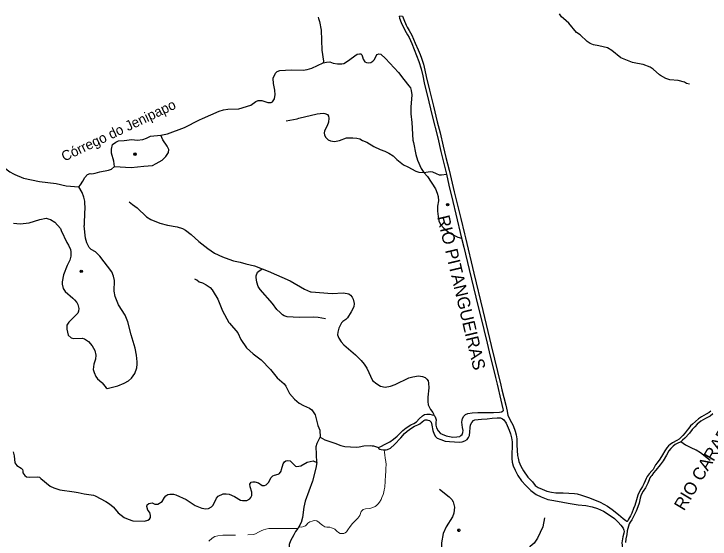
# Model space of a CAD drawing. Extents: x 267.7 to 296, y 7537.7 to 7565.8.
# Drawn here: x 273.16 to 278.74, y 7561.36 to 7565.57 of the extents above; entities that cross this region are included whole.
import ezdxf
from ezdxf.enums import TextEntityAlignment as Align

# ---------------------------------------------------------------- set-up
doc = ezdxf.new("R2010")
doc.units = 0
doc.header["$LTSCALE"] = 0.04
doc.header["$PDMODE"] = 32
doc.header["$PDSIZE"] = 0.02
doc.linetypes.add('SHORT_DASHED', pattern=[2.7, 1.5, -1.2])
for name, color, linetype, lineweight in [('1', 7, 'Continuous', 25), ('2', 7, 'Continuous', 25), ('21', 7, 'SHORT_DASHED', 13), ('62', 7, 'SHORT_DASHED', 13), ('7', 7, 'Continuous', 25)]:
    doc.layers.add(name, color=color, linetype=linetype, lineweight=lineweight)
doc.layers.add('54', color=7, linetype='Continuous')
doc.layers.add('61', color=7, linetype='Continuous')

msp = doc.modelspace()

# ---------------------------------------------------------------- linework, layer by layer
at = {"layer": '1'}
for points in [[(276.2507, 7565.5559), (276.2542, 7565.5396), (276.2661, 7565.5059), (276.2958, 7565.445), (276.3181, 7565.4069), (276.33, 7565.3861), (276.3532, 7565.3365), (276.3716, 7565.29), (276.4097, 7565.1914), (276.427, 7565.1335), (276.4394, 7565.078), (276.4523, 7565.022), (276.4899, 7564.8685), (276.5147, 7564.7575), (276.5598, 7564.5797), (276.585, 7564.4708), (276.6289, 7564.2909)], [(276.2787, 7565.5563), (276.2871, 7565.5302), (276.3064, 7565.4846), (276.3142, 7565.4671), (276.3322, 7565.4407), (276.3526, 7565.4046), (276.3797, 7565.3385), (276.4031, 7565.2868), (276.4182, 7565.249), (276.4302, 7565.2183), (276.4458, 7565.1708), (276.4572, 7565.1239), (276.4686, 7565.0717), (276.4945, 7564.9641), (276.5251, 7564.8336), (276.5558, 7564.7086), (276.5786, 7564.6203), (276.6027, 7564.5145), (276.6255, 7564.4219), (276.6508, 7564.321), (276.6922, 7564.1473), (276.7439, 7563.9333), (276.774, 7563.8113), (276.7818, 7563.7784)], [(276.6289, 7564.2909), (276.6499, 7564.2003), (276.6821, 7564.0705), (276.7059, 7563.969), (276.7511, 7563.7762)], [(276.7818, 7563.7784), (276.8485, 7563.4958), (276.92, 7563.1977), (276.9879, 7562.9152), (277.0661, 7562.5996), (277.0745, 7562.5624), (277.1057, 7562.4386), (277.1159, 7562.3901)], [(276.7511, 7563.7762), (276.7678, 7563.7055), (276.8119, 7563.5267), (276.8297, 7563.4489), (276.8822, 7563.237), (276.9015, 7563.1532), (276.955, 7562.9363), (276.9719, 7562.8665), (277.0224, 7562.6589), (277.0353, 7562.6059), (277.0665, 7562.4772), (277.0828, 7562.4078), (277.0848, 7562.3994), (277.0843, 7562.393)]]:
    msp.add_lwpolyline(points, dxfattribs=at)
at = {"layer": '2'}
for points in [[(276.528, 7562.3573), (276.5357, 7562.3502), (276.5434, 7562.3371), (276.5464, 7562.3206), (276.544, 7562.2981), (276.544, 7562.2767), (276.5493, 7562.2578), (276.5624, 7562.2317), (276.5831, 7562.2116), (276.595, 7562.2051), (276.6269, 7562.1932), (276.6803, 7562.182), (276.7122, 7562.1831), (276.7359, 7562.1879), (276.7454, 7562.1938), (276.7549, 7562.2039), (276.7602, 7562.2187), (276.7626, 7562.2341), (276.7596, 7562.259), (276.7537, 7562.3016), (276.7549, 7562.3176), (276.759, 7562.3318), (276.7691, 7562.3502), (276.7827, 7562.3632), (276.8011, 7562.3703), (276.8354, 7562.3774), (276.8822, 7562.3786), (277.0066, 7562.3798), (277.0558, 7562.3822), (277.07, 7562.3851), (277.0843, 7562.393)], [(277.1159, 7562.3901), (277.1165, 7562.3875), (277.1208, 7562.3592), (277.1262, 7562.3442), (277.1502, 7562.2997), (277.1634, 7562.2739), (277.1809, 7562.2306), (277.1893, 7562.1993), (277.1947, 7562.1693), (277.1947, 7562.12), (277.1971, 7562.0737), (277.2001, 7562.0359), (277.2037, 7562.0124), (277.2109, 7561.9854), (277.2247, 7561.9505), (277.2476, 7561.9127), (277.283, 7561.8616), (277.3185, 7561.8231), (277.3413, 7561.7955), (277.3648, 7561.778), (277.3954, 7561.7636), (277.4339, 7561.7486), (277.4706, 7561.7402), (277.5066, 7561.7366), (277.5655, 7561.7342), (277.6551, 7561.7299), (277.6785, 7561.7269), (277.7122, 7561.7179), (277.7759, 7561.6957), (277.8612, 7561.6596), (277.9213, 7561.6284), (277.9574, 7561.6007), (278.0091, 7561.5617), (278.0445, 7561.5304), (278.0668, 7561.5136), (278.074, 7561.5094), (278.08, 7561.5082)], [(278.7474, 7562.3898), (278.7336, 7562.3781), (278.7112, 7562.3669), (278.6728, 7562.3445), (278.6499, 7562.3285), (278.6243, 7562.3077), (278.6004, 7562.2854), (278.5865, 7562.2726), (278.5716, 7562.255), (278.5588, 7562.2385), (278.5423, 7562.2172), (278.5226, 7562.1953), (278.5061, 7562.1761), (278.4938, 7562.1655), (278.4746, 7562.1543), (278.4411, 7562.1367), (278.4214, 7562.1223), (278.4086, 7562.1111), (278.3958, 7562.0962), (278.3798, 7562.0723), (278.3612, 7562.0403), (278.3404, 7562.0057), (278.3169, 7561.9753), (278.3052, 7561.9604), (278.2935, 7561.9385), (278.285, 7561.9231), (278.2765, 7561.913), (278.2541, 7561.889), (278.237, 7561.8661), (278.229, 7561.8506), (278.2216, 7561.8325), (278.2125, 7561.8085), (278.2019, 7561.7872), (278.188, 7561.7654), (278.1726, 7561.7414), (278.1635, 7561.7169), (278.1513, 7561.6802), (278.1385, 7561.6327), (278.1294, 7561.6093), (278.115, 7561.5725), (278.1033, 7561.5502), (278.0889, 7561.5235), (278.0836, 7561.5118), (278.08, 7561.5082)], [(276.0867, 7562.1002), (276.1087, 7562.1097), (276.1347, 7562.1239), (276.1762, 7562.1446), (276.2046, 7562.166), (276.236, 7562.1897), (276.252, 7562.2051), (276.2792, 7562.2347), (276.3059, 7562.2572), (276.345, 7562.2809), (276.3681, 7562.2915), (276.3906, 7562.3058), (276.4125, 7562.3277), (276.4368, 7562.3526), (276.454, 7562.3626), (276.4735, 7562.3668), (276.4966, 7562.3656), (276.5162, 7562.362), (276.528, 7562.3573)], [(276.131, 7562.0789), (276.1466, 7562.0789), (276.1584, 7562.0825), (276.1803, 7562.0943), (276.2123, 7562.1239), (276.2656, 7562.1766), (276.2941, 7562.2116), (276.3142, 7562.2311), (276.3515, 7562.256), (276.3734, 7562.2702), (276.4001, 7562.2809), (276.4161, 7562.2886), (276.435, 7562.304), (276.4487, 7562.3152), (276.4605, 7562.3194), (276.4718, 7562.3206), (276.4818, 7562.3188), (276.4949, 7562.3146), (276.5002, 7562.3105), (276.5067, 7562.3028), (276.5126, 7562.2791), (276.5209, 7562.2353), (276.531, 7562.2068), (276.5416, 7562.1867), (276.5547, 7562.1749), (276.5843, 7562.1636), (276.6192, 7562.1506), (276.6548, 7562.1482), (276.7336, 7562.1423), (276.7561, 7562.1446), (276.7762, 7562.1518), (276.7952, 7562.1642), (276.8076, 7562.1778), (276.8153, 7562.1938), (276.8183, 7562.2234), (276.82, 7562.2554), (276.823, 7562.2809), (276.8319, 7562.2998), (276.8455, 7562.3146), (276.8585, 7562.3212), (276.9107, 7562.3271), (276.9569, 7562.3289), (276.9954, 7562.3336), (277.0351, 7562.3366), (277.0623, 7562.3354), (277.0801, 7562.3294), (277.0901, 7562.3212), (277.1073, 7562.2939), (277.1334, 7562.2382), (277.144, 7562.2086), (277.1523, 7562.1754), (277.1565, 7562.1441), (277.1559, 7562.102), (277.1541, 7562.054), (277.1541, 7562.0114), (277.1571, 7561.9823), (277.1654, 7561.951), (277.1814, 7561.9178), (277.2021, 7561.874), (277.2323, 7561.8319), (277.2661, 7561.7934), (277.3063, 7561.7537), (277.3496, 7561.7217), (277.3893, 7561.7034), (277.4414, 7561.6832), (277.4894, 7561.6749), (277.561, 7561.6619), (277.6061, 7561.653), (277.6848, 7561.6406), (277.7464, 7561.6341), (277.798, 7561.6234), (277.8388, 7561.6104), (277.8874, 7561.5879), (277.9182, 7561.5689), (277.9774, 7561.5286), (278.0065, 7561.4996), (278.0278, 7561.4765), (278.0444, 7561.451), (278.0515, 7561.4356)], [(278.765, 7562.3674), (278.7415, 7562.3498), (278.7064, 7562.3322), (278.6691, 7562.3093), (278.6393, 7562.2854), (278.6201, 7562.2656), (278.5988, 7562.2438), (278.5769, 7562.215), (278.5391, 7562.1735), (278.5221, 7562.157), (278.5067, 7562.1435)], [(278.5067, 7562.1435), (278.4773, 7562.1303), (278.4629, 7562.1218), (278.4475, 7562.1106), (278.4283, 7562.092), (278.4123, 7562.0717), (278.3931, 7562.0371), (278.3649, 7561.9929), (278.3431, 7561.9609), (278.3084, 7561.9162), (278.2898, 7561.8954), (278.2743, 7561.8751), (278.2663, 7561.8661), (278.2599, 7561.8554), (278.253, 7561.8384), (278.2429, 7561.8139), (278.2338, 7561.792), (278.2237, 7561.7761), (278.2056, 7561.7499), (278.1912, 7561.7196), (278.1832, 7561.6929), (278.1726, 7561.6535), (278.1635, 7561.6226), (278.1502, 7561.5896), (278.1289, 7561.5454), (278.114, 7561.5198), (278.1007, 7561.5012), (278.0927, 7561.4862), (278.0873, 7561.4687), (278.0788, 7561.4319), (278.0751, 7561.4015), (278.0682, 7561.3674), (278.0655, 7561.3387)], [(276.0867, 7562.1002), (276.0862, 7562.0937), (276.0885, 7562.0902), (276.0968, 7562.0842), (276.1069, 7562.0819), (276.1258, 7562.0789), (276.131, 7562.0789)], [(278.0515, 7561.4356), (278.0527, 7561.4262), (278.0515, 7561.4131), (278.0438, 7561.3841), (278.0361, 7561.3349), (278.0373, 7561.3172), (278.0402, 7561.2881), (278.0473, 7561.2301), (278.0639, 7561.1703), (278.074, 7561.1371), (278.0835, 7561.0885), (278.0918, 7561.0423), (278.0965, 7561.0026), (278.0947, 7560.9444)]]:
    msp.add_lwpolyline(points, dxfattribs=at)
at = {"layer": '21'}
for points in [[(275.4471, 7561.4626), (275.4699, 7561.4615), (275.4836, 7561.466), (275.4996, 7561.4721), (275.508, 7561.4797), (275.5186, 7561.4912), (275.5354, 7561.5018), (275.5537, 7561.5087), (275.5704, 7561.5125), (275.5917, 7561.511), (275.6108, 7561.4988), (275.6184, 7561.4889), (275.639, 7561.4729), (275.6565, 7561.4637), (275.6725, 7561.4599), (275.6953, 7561.4592), (275.7075, 7561.4546), (275.7258, 7561.4493), (275.7349, 7561.4439), (275.7517, 7561.4295), (275.7654, 7561.418), (275.7776, 7561.4104), (275.7898, 7561.4089), (275.8065, 7561.4104), (275.8179, 7561.4158), (275.8278, 7561.4241), (275.8393, 7561.4386), (275.8591, 7561.466), (275.8781, 7561.4896), (275.8979, 7561.511), (275.9185, 7561.533), (275.9345, 7561.5529), (275.9413, 7561.5696), (275.9467, 7561.5848), (275.9543, 7561.5947), (275.9634, 7561.6008), (275.9817, 7561.6077), (276.0152, 7561.6107), (276.0396, 7561.6168), (276.0586, 7561.626), (276.0693, 7561.6351), (276.0815, 7561.6481), (276.0921, 7561.6618), (276.1074, 7561.6823), (276.1134, 7561.6983), (276.1233, 7561.7219), (276.1279, 7561.7417), (276.1317, 7561.7585), (276.1363, 7561.7798), (276.1393, 7561.8286), (276.1409, 7561.8765), (276.1439, 7561.9055), (276.1454, 7561.9306), (276.1462, 7561.9618), (276.1431, 7561.987), (276.1393, 7562.0136), (276.1355, 7562.041), (276.1325, 7562.0601), (276.131, 7562.0789)], [(274.7266, 7561.3487), (274.7517, 7561.3723), (274.773, 7561.3853), (274.7974, 7561.3922), (274.8385, 7561.3952), (275.083, 7561.4005), (275.1005, 7561.4074), (275.1234, 7561.4203), (275.1462, 7561.431), (275.1637, 7561.4378), (275.1828, 7561.4439), (275.2079, 7561.4493), (275.2422, 7561.4508), (275.3435, 7561.45), (275.4381, 7561.4484)]]:
    msp.add_lwpolyline(points, dxfattribs=at)
msp.add_point((276.729, 7561.4355), dxfattribs=at)
at = {"layer": '54'}
for p in [(274.1337, 7564.4501), (276.6391, 7564.0448), (273.7043, 7563.5115)]:
    msp.add_point(p, dxfattribs=at)
at = {"layer": '62'}
msp.add_line((276.2507, 7565.5559), (276.2787, 7565.5563), dxfattribs=at)
at = {"layer": '7'}
msp.add_line((276.0443, 7562.1123), (276.0867, 7562.1002), dxfattribs=at)
for points in [[(278.5776, 7565.0106), (278.5773, 7565.0107), (278.5528, 7565.0167), (278.5368, 7565.0272), (278.487, 7565.0394), (278.4188, 7565.047), (278.3887, 7565.0552), (278.3439, 7565.0796), (278.3371, 7565.0858), (278.2865, 7565.1317), (278.2623, 7565.147), (278.2072, 7565.1684), (278.1607, 7565.1771), (278.1198, 7565.1847), (278.0274, 7565.2212), (277.9555, 7565.2795), (277.9192, 7565.301), (277.8518, 7565.3187), (277.8069, 7565.3263), (277.7819, 7565.3363), (277.7578, 7565.3517), (277.7005, 7565.4055), (277.6705, 7565.4261), (277.6099, 7565.5003), (277.5669, 7565.5369), (277.5518, 7565.5495), (277.5353, 7565.574)], [(275.6019, 7565.5467), (275.6049, 7565.5381), (275.6132, 7565.5145), (275.6266, 7565.4435), (275.6323, 7565.2827), (275.6434, 7565.1957), (275.6428, 7565.1809)], [(275.6428, 7565.1809), (275.6685, 7565.1883), (275.6942, 7565.1893), (275.7231, 7565.1794), (275.7571, 7565.1742), (275.7915, 7565.1742), (275.8064, 7565.1771), (275.8369, 7565.194), (275.9147, 7565.2503), (275.9322, 7565.2543), (275.9425, 7565.2533), (275.9517, 7565.2451), (275.9576, 7565.2312), (275.9631, 7565.2126), (275.9771, 7565.1902), (275.9894, 7565.1839), (276.0069, 7565.1814), (276.0232, 7565.1839), (276.0411, 7565.1944), (276.0543, 7565.2078), (276.0677, 7565.2379)], [(276.0677, 7565.2379), (276.0759, 7565.2482), (276.0893, 7565.2533), (276.1043, 7565.2504), (276.1425, 7565.2161), (276.2457, 7565.1058), (276.2875, 7565.0477), (276.3286, 7564.9989), (276.3407, 7564.9823), (276.3471, 7564.9599), (276.3536, 7564.9244), (276.3441, 7564.8263), (276.3441, 7564.7725), (276.352, 7564.7035), (276.3617, 7564.5618), (276.3656, 7564.5421), (276.3841, 7564.448), (276.3974, 7564.4014), (276.4278, 7564.3355), (276.4486, 7564.3021)], [(274.341, 7564.6029), (274.396, 7564.614), (274.5299, 7564.6637), (274.652, 7564.7251), (274.6747, 7564.7365), (274.8084, 7564.7942), (274.8427, 7564.8048), (274.8771, 7564.8095), (274.9651, 7564.8136), (275.0622, 7564.8414), (275.1025, 7564.8725), (275.1211, 7564.8805), (275.1503, 7564.8797), (275.1991, 7564.8638), (275.2261, 7564.8632), (275.2366, 7564.8705), (275.2522, 7564.8947), (275.2524, 7564.8963), (275.2571, 7564.9261), (275.2539, 7564.9636), (275.2428, 7565.0158), (275.2426, 7565.0554), (275.2426, 7565.0581), (275.26, 7565.0993), (275.2743, 7565.1136), (275.2936, 7565.1214), (275.3855, 7565.1264), (275.483, 7565.124), (275.5149, 7565.1278), (275.5522, 7565.1405), (275.6428, 7565.1809)], [(275.3444, 7564.7168), (275.4333, 7564.7343), (275.4459, 7564.7373), (275.5939, 7564.7728), (275.6412, 7564.7776), (275.6559, 7564.776), (275.677, 7564.7669), (275.6841, 7564.7537), (275.6873, 7564.7377), (275.6852, 7564.7051), (275.675, 7564.6766), (275.6532, 7564.6375), (275.6499, 7564.6192), (275.6514, 7564.6056), (275.6598, 7564.5859), (275.6828, 7564.5636), (275.6996, 7564.5558), (275.7315, 7564.5511), (275.774, 7564.5588), (275.8301, 7564.5797), (275.8787, 7564.5813), (275.9127, 7564.5789), (275.9355, 7564.5725), (275.9584, 7564.5594), (275.9919, 7564.5459), (276.0471, 7564.5119), (276.0985, 7564.487), (276.1368, 7564.4743), (276.146, 7564.4699), (276.1693, 7564.4588), (276.2036, 7564.4361), (276.231, 7564.4079), (276.2849, 7564.3639), (276.3201, 7564.3491), (276.3846, 7564.3147), (276.4091, 7564.3061), (276.4486, 7564.3021)], [(273.97, 7564.3504), (273.9661, 7564.3938), (273.9454, 7564.4584), (273.9454, 7564.4907), (273.9545, 7564.5272), (273.981, 7564.5468), (274.0015, 7564.557), (274.0466, 7564.5583), (274.1081, 7564.5669), (274.152, 7564.5622), (274.1972, 7564.5677), (274.2259, 7564.5772), (274.2589, 7564.5941), (274.341, 7564.6029)], [(273.97, 7564.3504), (274.1026, 7564.342), (274.2047, 7564.3539), (274.2759, 7564.3585), (274.3038, 7564.3746), (274.3516, 7564.4021), (274.3824, 7564.4311), (274.4026, 7564.4624), (274.4051, 7564.4863), (274.3934, 7564.5151), (274.3575, 7564.5661), (274.341, 7564.6029)], [(273.0769, 7564.3511), (273.0852, 7564.3422), (273.1311, 7564.3079), (273.1617, 7564.291), (273.1713, 7564.2857), (273.2409, 7564.2583), (273.3691, 7564.23), (273.5033, 7564.2158), (273.5828, 7564.196), (273.6844, 7564.1868)], [(273.6844, 7564.1868), (273.6977, 7564.2033), (273.7152, 7564.2341), (273.732, 7564.2632), (273.7545, 7564.2879), (273.7754, 7564.2939), (273.789, 7564.2925), (273.8149, 7564.2965), (273.8529, 7564.3092), (273.9227, 7564.3215), (273.9465, 7564.3309), (273.97, 7564.3502), (273.97, 7564.3504)], [(276.4486, 7564.3021), (276.4836, 7564.3092), (276.506, 7564.3121), (276.5193, 7564.309), (276.5481, 7564.2946), (276.5722, 7564.2853), (276.5898, 7564.2845), (276.6289, 7564.2909)], [(276.4486, 7564.3021), (276.479, 7564.2715), (276.5409, 7564.1717), (276.5551, 7564.1383), (276.5645, 7564.1119), (276.5666, 7564.076), (276.5594, 7564.0319), (276.5592, 7563.9933), (276.5626, 7563.9495), (276.5699, 7563.9147), (276.5712, 7563.9088), (276.5853, 7563.8831), (276.6089, 7563.8571), (276.6567, 7563.8172), (276.7203, 7563.7851), (276.7511, 7563.7762)], [(273.7246, 7564.1065), (273.7101, 7564.1421), (273.6844, 7564.1868)], [(273.7284, 7563.8751), (273.7287, 7563.8824), (273.7332, 7563.988), (273.7364, 7564.0071), (273.733, 7564.0731), (273.7246, 7564.1065)], [(274.087, 7564.0685), (274.1151, 7564.0467), (274.1512, 7564.0187), (274.2268, 7563.9488), (274.2621, 7563.9266), (274.3324, 7563.8964), (274.395, 7563.8797), (274.4717, 7563.8688), (274.516, 7563.8538), (274.5379, 7563.8415), (274.5835, 7563.8068), (274.6447, 7563.7496), (274.7171, 7563.6937), (274.7723, 7563.6569), (274.8351, 7563.6266), (274.8555, 7563.6193), (274.924, 7563.595), (274.9777, 7563.5855), (275.023, 7563.5699), (275.092, 7563.5541), (275.1546, 7563.5305)], [(273.1599, 7563.8968), (273.2137, 7563.8919), (273.2871, 7563.9), (273.3717, 7563.9253), (273.4215, 7563.9365), (273.438, 7563.9323), (273.4567, 7563.9264), (273.4921, 7563.9062), (273.5363, 7563.8544), (273.5441, 7563.8373), (273.5884, 7563.7411), (273.6014, 7563.7211), (273.6167, 7563.6857), (273.6199, 7563.6669), (273.6197, 7563.6333), (273.6197, 7563.6325), (273.6126, 7563.6), (273.5907, 7563.5586), (273.5603, 7563.4823), (273.5497, 7563.4263), (273.5497, 7563.408), (273.5592, 7563.3733), (273.5738, 7563.349), (273.6354, 7563.2965), (273.6505, 7563.2836), (273.6689, 7563.2611), (273.6772, 7563.2456), (273.6834, 7563.2138), (273.6823, 7563.1912), (273.6754, 7563.1759), (273.6036, 7563.1042), (273.5884, 7563.0789), (273.5881, 7563.0529), (273.588, 7563.0473), (273.5995, 7562.9993), (273.6219, 7562.9766), (273.6433, 7562.9727), (273.7104, 7562.9742), (273.7295, 7562.9685), (273.7615, 7562.9481), (273.7903, 7562.9147), (273.8122, 7562.875), (273.8193, 7562.8402), (273.8166, 7562.8075), (273.8051, 7562.7675), (273.8002, 7562.7253), (273.8076, 7562.6989), (273.8213, 7562.667), (273.8341, 7562.6504), (273.869, 7562.6187), (273.8709, 7562.617), (273.9036, 7562.577), (273.9108, 7562.5722), (273.9956, 7562.5934), (274.0477, 7562.6137), (274.0817, 7562.6324), (274.1071, 7562.6548), (274.1331, 7562.6921), (274.1493, 7562.7382), (274.1514, 7562.7655), (274.1529, 7562.7853), (274.1476, 7562.8393), (274.1367, 7562.8953), (274.1029, 7563.0012), (274.0777, 7563.1055), (274.0559, 7563.1585), (274.0025, 7563.2415), (273.9757, 7563.3097), (273.9678, 7563.3516), (273.9678, 7563.3773), (273.9678, 7563.3848), (273.971, 7563.4041), (273.9692, 7563.4363), (273.9619, 7563.4714), (273.9493, 7563.5056), (273.8526, 7563.6336), (273.8169, 7563.6662), (273.7841, 7563.6863), (273.7681, 7563.7021), (273.7484, 7563.7399), (273.738, 7563.7755), (273.7284, 7563.8751)], [(275.6599, 7563.1314), (275.6019, 7563.141), (275.5643, 7563.1434), (275.4509, 7563.1402), (275.353, 7563.1467), (275.3305, 7563.1539), (275.3163, 7563.1628), (275.2981, 7563.18), (275.2716, 7563.205), (275.2367, 7563.2534), (275.1362, 7563.3658), (275.1225, 7563.3892), (275.1101, 7563.4228), (275.1049, 7563.4616), (275.1063, 7563.4755), (275.1166, 7563.5034), (275.1253, 7563.5131), (275.1546, 7563.5305)], [(275.1546, 7563.5305), (275.2003, 7563.5133), (275.3781, 7563.4341), (275.4915, 7563.367), (275.5404, 7563.3459), (275.5459, 7563.3455), (275.7147, 7563.3326), (275.8021, 7563.3381), (275.8349, 7563.3333), (275.847, 7563.3298), (275.8614, 7563.3185), (275.8737, 7563.3031), (275.883, 7563.2867), (275.89, 7563.2539), (275.8876, 7563.2264), (275.8668, 7563.1866), (275.8367, 7563.1389), (275.8224, 7563.1235), (275.8008, 7563.1081), (275.7899, 7563.0968), (275.7669, 7563.055), (275.7584, 7563.024), (275.7576, 7563.0025), (275.7674, 7562.9752), (275.7852, 7562.9453), (275.8065, 7562.9221), (275.9022, 7562.8423), (275.9459, 7562.7971), (275.9706, 7562.7667), (275.9912, 7562.7351), (276.0374, 7562.6372), (276.0713, 7562.6079), (276.1009, 7562.5892), (276.1393, 7562.5833), (276.1824, 7562.5904), (276.2201, 7562.6035), (276.3278, 7562.6565), (276.36, 7562.6662), (276.4047, 7562.6726), (276.4376, 7562.6672), (276.4595, 7562.6591), (276.4732, 7562.6462), (276.4844, 7562.6329), (276.4868, 7562.615), (276.4884, 7562.5765), (276.4806, 7562.5029), (276.4806, 7562.468), (276.4844, 7562.4415), (276.5007, 7562.4023), (276.5211, 7562.3789), (276.5262, 7562.3697), (276.528, 7562.3573)], [(274.6105, 7563.4515), (274.6261, 7563.4416), (274.6297, 7563.4437), (274.649, 7563.4272), (274.6757, 7563.419), (274.7044, 7563.4031), (274.7356, 7563.3802), (274.7526, 7563.3614), (274.7607, 7563.3482), (274.7976, 7563.2886), (274.8355, 7563.1939), (274.8874, 7563.1003), (274.8912, 7563.0957), (274.957, 7563.0176), (274.9818, 7562.9651), (275.0281, 7562.8969), (275.0806, 7562.849), (275.1455, 7562.8002), (275.2203, 7562.7247), (275.2734, 7562.658), (275.3296, 7562.609), (275.3436, 7562.5893), (275.3728, 7562.5324), (275.4112, 7562.4875), (275.4504, 7562.4547), (275.4851, 7562.435), (275.533, 7562.4142), (275.5524, 7562.4005), (275.5787, 7562.3601), (275.6, 7562.2742), (275.6148, 7562.2366), (275.6177, 7562.1811)], [(275.5922, 7561.9786), (275.5923, 7561.9785), (275.5859, 7562.1073), (275.5936, 7562.1325), (275.6177, 7562.1811)], [(275.6177, 7562.1811), (275.6557, 7562.1599), (275.7363, 7562.1347), (275.7823, 7562.1146), (275.8143, 7562.1063), (275.9062, 7562.1013), (275.9312, 7562.1032), (275.9691, 7562.1132), (276.0248, 7562.1155), (276.0334, 7562.1133), (276.0443, 7562.1123)], [(278.7425, 7561.9934), (278.6656, 7562.056), (278.6296, 7562.0765), (278.5896, 7562.095), (278.5529, 7562.1142), (278.5465, 7562.1176), (278.5067, 7562.1435)], [(273.1578, 7562.0629), (273.1673, 7562.031), (273.1708, 7561.9757), (273.1879, 7561.9547), (273.2225, 7561.9328), (273.2317, 7561.9236), (273.2358, 7561.9113), (273.2363, 7561.8951), (273.2504, 7561.8732), (273.2662, 7561.865), (273.2882, 7561.8611), (273.3544, 7561.863), (273.3683, 7561.861), (273.3792, 7561.8501), (273.4556, 7561.7902), (273.4852, 7561.7757), (273.5329, 7561.7604), (273.6477, 7561.7444), (273.6792, 7561.7375), (273.7259, 7561.7272), (273.8014, 7561.7167), (273.8164, 7561.7117), (273.902, 7561.6673), (273.931, 7561.648), (273.9601, 7561.6221), (273.9617, 7561.6202), (273.9999, 7561.576), (274.047, 7561.5371), (274.0796, 7561.5233), (274.1174, 7561.5124), (274.2095, 7561.5093), (274.2383, 7561.5154), (274.2504, 7561.5246), (274.2597, 7561.5378), (274.2592, 7561.5551), (274.2522, 7561.5768), (274.2377, 7561.5966), (274.2279, 7561.6267), (274.2327, 7561.64), (274.2455, 7561.6511), (274.2706, 7561.6544), (274.2941, 7561.6456), (274.3164, 7561.6449), (274.3519, 7561.6663), (274.3705, 7561.6972), (274.3819, 7561.7102), (274.3983, 7561.7212), (274.4122, 7561.7245), (274.4433, 7561.7238), (274.4614, 7561.7193), (274.5435, 7561.6817), (274.617, 7561.6346), (274.671, 7561.6136), (274.7015, 7561.6082), (274.7233, 7561.6093), (274.7461, 7561.6227), (274.7588, 7561.6343), (274.772, 7561.6572), (274.7863, 7561.6924), (274.8, 7561.7101), (274.8408, 7561.7262), (274.8647, 7561.7279), (274.8895, 7561.7255), (274.9313, 7561.7056), (274.9792, 7561.6777), (274.9959, 7561.6743), (275.0303, 7561.6744), (275.0532, 7561.6882), (275.0633, 7561.6992), (275.0705, 7561.7135), (275.0713, 7561.7422), (275.0572, 7561.7846), (275.0556, 7561.8055), (275.0661, 7561.8199), (275.0786, 7561.8243), (275.0952, 7561.8242), (275.1247, 7561.8156), (275.1539, 7561.7949), (275.1723, 7561.7933), (275.1845, 7561.7991), (275.2056, 7561.8213), (275.2229, 7561.855), (275.2328, 7561.8668), (275.2377, 7561.8714), (275.2522, 7561.8762), (275.2817, 7561.8851), (275.2912, 7561.8916), (275.3043, 7561.9079), (275.3095, 7561.9234), (275.3217, 7561.9669), (275.3316, 7561.9839), (275.3439, 7561.9925), (275.3575, 7561.9958), (275.3774, 7561.992), (275.4191, 7561.9491)], [(275.4191, 7561.9491), (275.4319, 7561.9473), (275.4623, 7561.9518), (275.5126, 7561.9815), (275.5632, 7561.9925), (275.5922, 7561.9786)], [(275.5922, 7561.9786), (275.584, 7561.932), (275.557, 7561.8292), (275.4981, 7561.6685), (275.4862, 7561.6206), (275.4755, 7561.5389), (275.4654, 7561.4977), (275.4471, 7561.4626)], [(276.5752, 7561.7649), (276.6507, 7561.7042), (276.6718, 7561.6815), (276.6842, 7561.6621), (276.6953, 7561.6202), (276.689, 7561.5726), (276.6786, 7561.5438), (276.6266, 7561.4636), (276.604, 7561.4099), (276.5893, 7561.3349), (276.5912, 7561.2748), (276.6147, 7561.213), (276.6549, 7561.1485), (276.6821, 7561.0705), (276.7077, 7561.0231)], [(277.4158, 7561.536), (277.4018, 7561.4623), (277.3582, 7561.3727), (277.3323, 7561.3334), (277.3019, 7561.3055), (277.2399, 7561.2441), (277.2317, 7561.2319), (277.2168, 7561.2013), (277.2026, 7561.1472), (277.1926, 7561.1261), (277.1781, 7561.1092), (277.1429, 7561.0793), (277.0834, 7561.043), (277.052, 7561.0179), (277.031, 7560.9947), (277.0209, 7560.9771), (277.0137, 7560.9544), (277.0134, 7560.9347), (276.9997, 7560.9042), (276.9843, 7560.8818), (276.9685, 7560.8647)], [(275.4381, 7561.4484), (275.4214, 7561.4267), (275.4073, 7561.399), (275.3927, 7561.376), (275.3793, 7561.3503), (275.3694, 7561.3213), (275.3673, 7561.2611), (275.3741, 7561.225), (275.3577, 7561.1355), (275.3153, 7561.0475), (275.2756, 7560.9765), (275.2629, 7560.9316), (275.2591, 7560.8949), (275.2636, 7560.8645), (275.2989, 7560.7764)], [(275.4471, 7561.4626), (275.4429, 7561.4546), (275.4393, 7561.4499), (275.4381, 7561.4484)]]:
    msp.add_lwpolyline(points, dxfattribs=at)

# ---------------------------------------------------------------- texts
at = {"layer": '61'}
for s, height, rotation, p in [('Córrego do Jenipapo', 0.08, 25.463, (274.0192, 7564.6046)), ('RIO PITANGUEIRAS', 0.1, 283.367, (276.7013, 7563.3292)), ('RIO CARAPEBA OU CANAL DA  ANDREZA', 0.1, 59.138, (279.2153, 7562.7274))]:
    msp.add_text(s, height=height, rotation=rotation, dxfattribs=at).set_placement(p, align=Align.CENTER)

doc.saveas('drawing.dxf')
